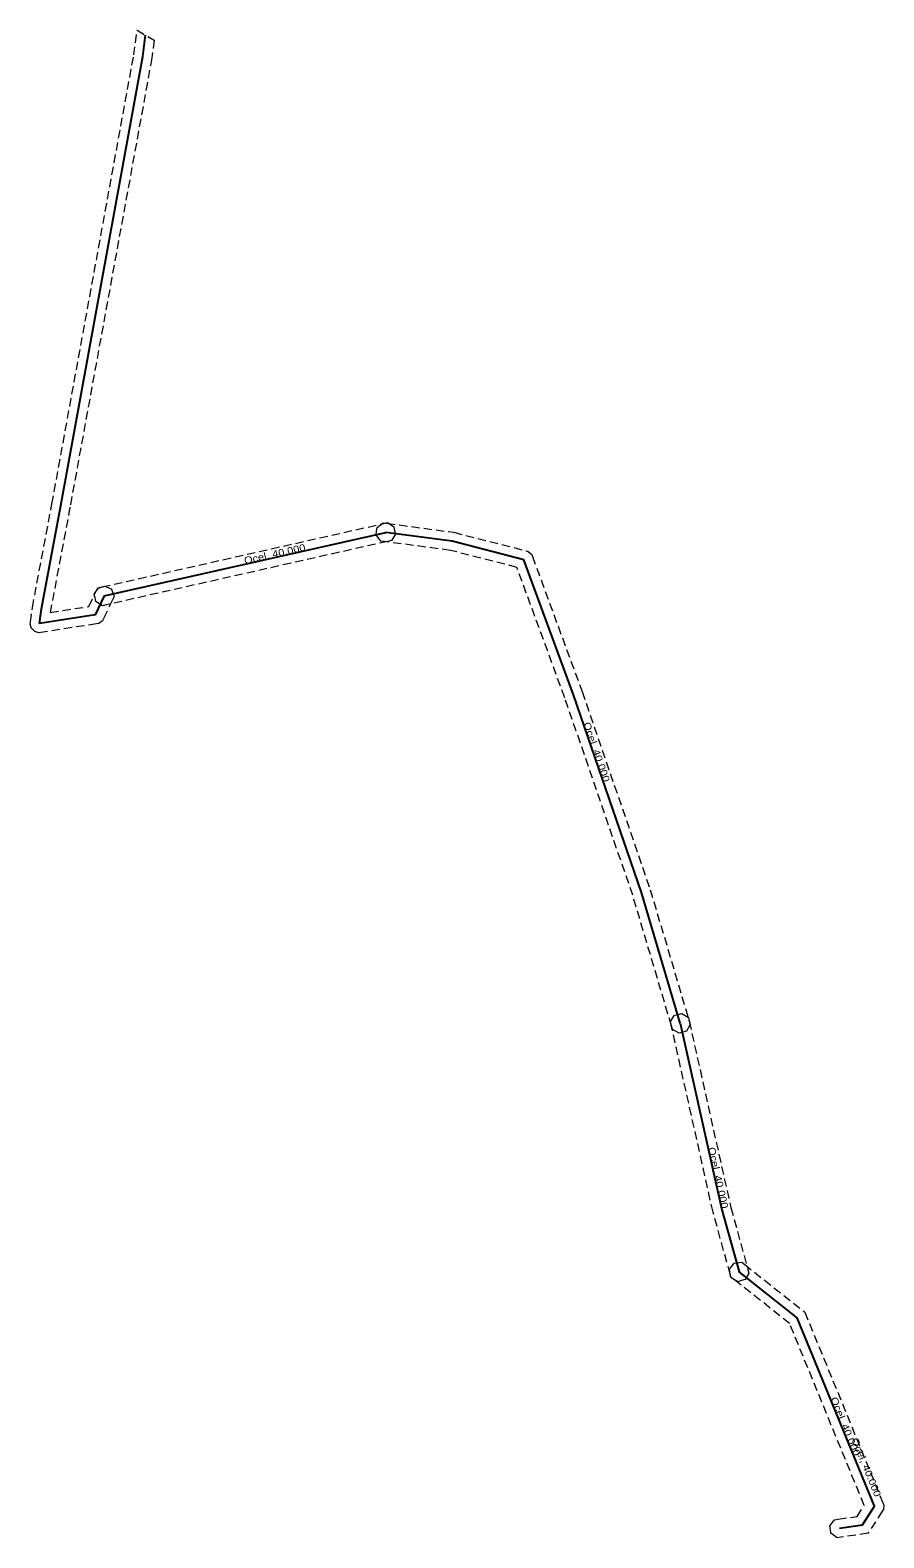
# Model space of a CAD drawing. Extents: x -640775 to -624586, y -1148563 to -1138811.
# Drawn here: x -638157.8 to -638064.8, y -1140187.8 to -1140023.6 of the extents above; entities that cross this region are included whole.
import ezdxf
from ezdxf.enums import TextEntityAlignment as Align

# ---------------------------------------------------------------- set-up
doc = ezdxf.new("R2010")
doc.units = 0
doc.header["$LTSCALE"] = 0.3
doc.linetypes.add('MEDIUM_DASHED', pattern=[4.5, 3, -1.5])
doc.layers.add('1', color=7, linetype='MEDIUM_DASHED', lineweight=13)
doc.layers.add('24', color=7, linetype='Continuous', lineweight=40)
doc.layers.add('30', color=7, linetype='Continuous')

msp = doc.modelspace()

# ---------------------------------------------------------------- linework, layer by layer
at = {"layer": '1'}
for points in [[(-638146.131, -1140023.559), (-638144.261, -1140024.668), (-638144.512, -1140026.575), (-638153.437, -1140075.552), (-638155.552, -1140086.789), (-638155.581, -1140087.007), (-638151.367, -1140086.353), (-638150.624, -1140084.782), (-638150.447, -1140084.408), (-638149.666, -1140084.129), (-638149.292, -1140084.306), (-638148.918, -1140084.483), (-638148.639, -1140085.264), (-638148.816, -1140085.638), (-638149.786, -1140087.688), (-638149.892, -1140087.913), (-638150.291, -1140088.21), (-638150.537, -1140088.248), (-638156.597, -1140089.188), (-638156.831, -1140089.224), (-638157.281, -1140089.08), (-638157.45, -1140088.914), (-638157.619, -1140088.749), (-638157.773, -1140088.302), (-638157.741, -1140088.067), (-638157.528, -1140086.471), (-638155.403, -1140075.188), (-638146.488, -1140026.265)], [(-638150.787, -1140085.026), (-638150.344, -1140084.326), (-638149.94, -1140084.235), (-638119.26, -1140077.315), (-638118.856, -1140077.223), (-638118.156, -1140077.666), (-638118.065, -1140078.07), (-638117.973, -1140078.474), (-638118.416, -1140079.174), (-638118.82, -1140079.265), (-638149.5, -1140086.185), (-638149.904, -1140086.277), (-638150.604, -1140085.834), (-638150.695, -1140085.43)], [(-638087.063, -1140132.857), (-638087.791, -1140132.461), (-638087.909, -1140132.064), (-638092.123, -1140117.835), (-638099.532, -1140096.305), (-638104.748, -1140082.098), (-638111.991, -1140080.243), (-638119.173, -1140079.281), (-638119.583, -1140079.226), (-638120.086, -1140078.567), (-638120.031, -1140078.157), (-638119.976, -1140077.747), (-638119.317, -1140077.244), (-638118.907, -1140077.299), (-638111.609, -1140078.277), (-638103.742, -1140080.291), (-638103.503, -1140080.353), (-638103.136, -1140080.684), (-638103.051, -1140080.915), (-638097.648, -1140095.635), (-638090.217, -1140117.225), (-638085.991, -1140131.496), (-638085.873, -1140131.893), (-638086.269, -1140132.621), (-638086.666, -1140132.739)], [(-638086.764, -1140130.714), (-638086.064, -1140131.158), (-638085.974, -1140131.562), (-638081.44, -1140151.867), (-638079.576, -1140158.593), (-638079.465, -1140158.992), (-638079.874, -1140159.713), (-638080.273, -1140159.824), (-638080.672, -1140159.935), (-638081.393, -1140159.526), (-638081.504, -1140159.127), (-638083.38, -1140152.353), (-638087.926, -1140131.998), (-638088.016, -1140131.594), (-638087.572, -1140130.894), (-638087.168, -1140130.804)], [(-638070.649, -1140186.536), (-638070.156, -1140185.871), (-638069.746, -1140185.811), (-638067.685, -1140185.507), (-638066.913, -1140184.307), (-638075.036, -1140164.492), (-638081.161, -1140159.644), (-638081.486, -1140159.387), (-638081.581, -1140158.564), (-638081.324, -1140158.239), (-638081.067, -1140157.914), (-638080.244, -1140157.819), (-638079.919, -1140158.076), (-638073.384, -1140163.248), (-638064.865, -1140184.031), (-638064.772, -1140184.258), (-638064.816, -1140184.745), (-638064.949, -1140184.951), (-638066.495, -1140187.353), (-638069.454, -1140187.789), (-638069.864, -1140187.849), (-638070.529, -1140187.356), (-638070.589, -1140186.946)]]:
    msp.add_lwpolyline(points, close=True, dxfattribs=at)
at = {"layer": '24', "lineweight": 25}
msp.add_line((-638149.72, -1140085.21), (-638119.04, -1140078.29), dxfattribs=at)
for points in [[(-638156.75, -1140088.2), (-638156.54, -1140086.63), (-638154.42, -1140075.37), (-638145.5, -1140026.42), (-638145.196, -1140024.114)], [(-638086.95, -1140131.78), (-638091.17, -1140117.53), (-638098.59, -1140095.97), (-638103.99, -1140081.26), (-638111.8, -1140079.26), (-638119.04, -1140078.29)], [(-638149.72, -1140085.21), (-638150.69, -1140087.26), (-638156.75, -1140088.2)], [(-638086.95, -1140131.78), (-638082.41, -1140152.11), (-638080.54, -1140158.86)], [(-638069.6, -1140186.8), (-638067.09, -1140186.43), (-638065.79, -1140184.41), (-638074.21, -1140163.87), (-638080.54, -1140158.86)]]:
    msp.add_lwpolyline(points, dxfattribs=at)

# ---------------------------------------------------------------- texts
at = {"layer": '30', "width": 1.2}
for rotation, p in [(12.711, (-638134.38, -1140081.75)), (288.991, (-638097.512, -1140099.103)), (282.588, (-638083.917, -1140145.363)), (292.29, (-638070.594, -1140172.69))]:
    msp.add_text('Ocel, 40.000', height=0.75, rotation=rotation, dxfattribs=at).set_placement(p)
msp.add_text('Ocel, 40.000', height=0.75, rotation=292.208, dxfattribs=at).set_placement((-638067.029, -1140180.294), align=Align.CENTER)

doc.saveas('drawing.dxf')
